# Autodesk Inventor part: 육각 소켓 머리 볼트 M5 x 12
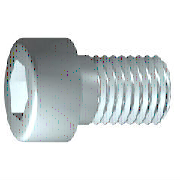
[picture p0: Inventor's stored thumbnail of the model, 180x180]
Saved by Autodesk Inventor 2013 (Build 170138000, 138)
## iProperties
Created: 2012-02
Part Number: 육각 소켓 머리 볼트 M5 x 12
Material: 강철, 연강
Description: 6각 소켓 머리 캡 나사
Document SubType Name: Modeling
Standard: ISO 4762
Designer: mdu-01
Standard Revision: Fourth edition 2004-03-01
Standards Organization: ISO
Language: ko-KR
Size Designation: M5 x 12
Categories: <MemberInstance><Categories><Category DisplayName="조임쇠" InternalName="e4da775c-781d-43d5-af7c-5136215cf5a6" Mnemonic="FSTN"><Category DisplayName="볼트" InternalN
Density: 7.75 g/cm^3
Author: mdu-01
IsCustomPart: 1
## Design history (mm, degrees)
sketch "스케치1"
  geometry: L1 (-1.167, 0)-(12, 0); L2 (12, 0)-(12, 2.5); L3 (12, 2.5)-(2, 2.5); L4 (2, 2.5)-(1.509, 2.5); L5 (1.509, 2.5)-(0, 2.5); L6 (0, 2.5)-(0, 4.25); L7 (0, 4.25)-(-5, 4.25); L8 (-5, 4.25)-(-5, 2.309); L9 (-5, 2.309)-(-2.5, 2.309); L10 (-2.5, 2.309)-(-1.167, 0); L11 (-8.4, 0)-(15.4, 0) reference; L12 (0, -0.85)-(0, 5.1) reference; L13 (2, 2.5)-(0, 2.5)
  constraints: 22 end point, 6 parallel, 2 collinear, 2 perpendicular, 1 horizontal, 1 point on line
  dimensions: "d1" = 10 distance from line of L3.end L2 (= GEL); "d2" = 0.49086 distance of L4.end L3.end (computed from GAL); "d3" = 5 distance between parallel lines of L8 L6 (= KOH); "d4" = 2.5 distance of L8.end L9.end (= INTI); "d5" = 60 deg angle of L10 L1; "d6" = 5 diameter of L3 L1 (= GD); "d7" = 5 diameter of L5 L1 (= BDM); "d8" = 4.6188 diameter of L9 L1 (= 1.1547 x SW); "d9" = 8.5 diameter of L7 L1 (= KOD); "d26" = 12 distance between parallel lines of L12 L2 (= NLG)
revolve "본체" sketch "스케치1" stored, may be unused: angle "d10" = 90 deg
sketch "스케치2"
  geometry: L1 (0, -5.95)-(0, 5.95) reference; L2 (-5.95, 0)-(5.95, 0) reference; L3 (2.309, 0)-(1.155, -2); L4 (1.155, -2)-(-1.155, -2); L5 (-1.155, -2)-(-2.309, 0); L6 (-2.309, 0)-(-1.155, 2); L7 (-1.155, 2)-(1.155, 2); L8 (1.155, 2)-(2.309, 0); 2 further points
  constraints: 12 end point, 1 coincident, 1 horizontal alignment, 1 point on line, 12 other
extrude "슬롯" join sketch "스케치2" stored distance "d11" = 10; taper "d12" = 0 deg
workplane "Work Plane1"
fillet "Fillet2" dims "d30" = 0.1 (= R)
body "Solid1"
fillet "모깎기1" dims "d17" = 0.5 (= RR)
feature "스레드" dims "d13" = 10 (= GEL), "d14" = 0
chamfer "모따기1" distance "d15" = 0.49076 (= -0.5 x SPD + 0.5 x GD); stored, may be unused: second distance "d16" = 0.49076 (= GUL), angle "d27" = 45 deg
other parameters: "GD" = 5 [user parameter; used in 2 equation terms], "NLG" = 12 [user parameter; used in 1 equation term], "GEL" = 10 [user parameter; used in 2 equation terms], "KOD" = 8.5 [user parameter; used in 1 equation term], "KOH" = 5 [user parameter; used in 1 equation term], "INTI" = 2.5 [user parameter; used in 1 equation term], "GAL" = 0.49076 (= 0.61345 x PTC) [user parameter; used in 1 equation term], "GUL" = 0.49076 (= 0.61345 x PTC) [user parameter; used in 1 equation term], "BDM" = 5 (= NND) [user parameter; used in 1 equation term], "SW" = 4 [user parameter; used in 2 equation terms], "RR" = 0.5 [user parameter; used in 1 equation term], "SPD" = 4.01848 (= NND - 1.2269 x PTC) [user parameter; used in 1 equation term], "d19" = 0, "d28" = 0, "d29" = 0, "R" = 0.1 [user parameter; used in 1 equation term], "TOA" = 30 deg [user parameter], "GD1" = 4.01848 (= THREADDIA - 1.2269 x PTC) [user parameter], "THREADDIA" = 5 [user parameter; used in 1 equation term], "FAWI" = 45 deg [user parameter], "TPU" = 12.5 (computed from PTC) [user parameter], "PTC" = 0.8 [user parameter; used in 5 equation terms], "NND" = 5 [user parameter; used in 2 equation terms], "E0" = 4.62 (= 1.155 x SW) [user parameter]
